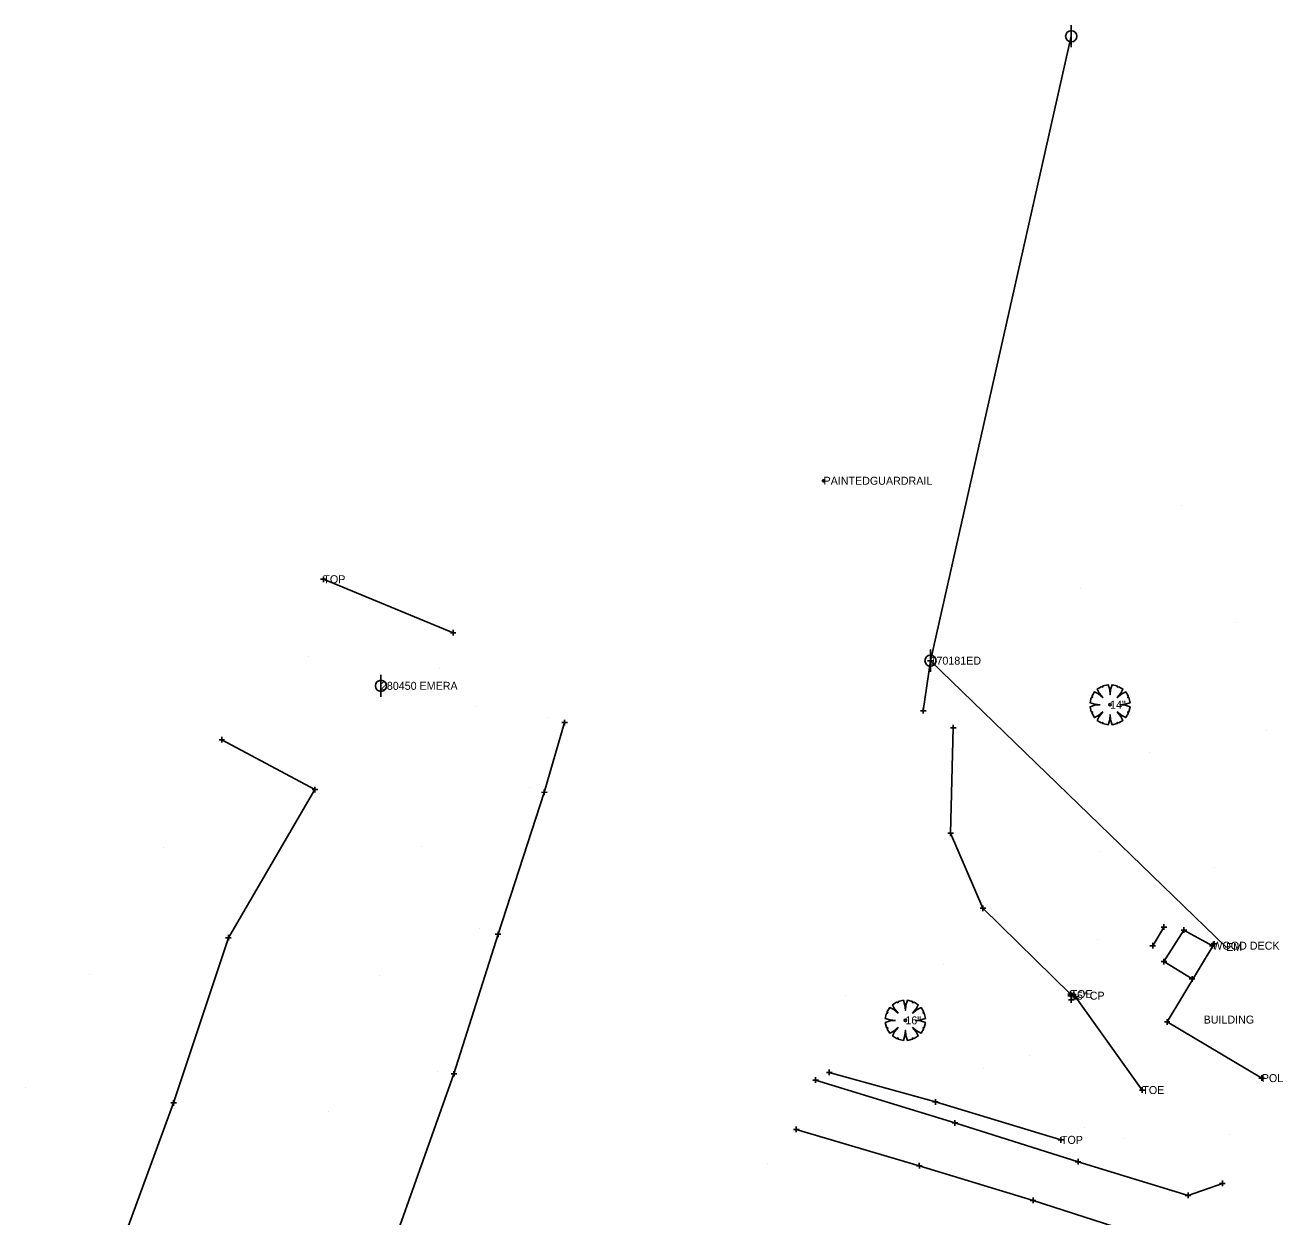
# Model space of a CAD drawing. Extents: x 1738496 to 1739092, y 463766 to 465141.
# Drawn here: x 1738806.9 to 1739089.9, y 464872.7 to 465140.8 of the extents above; entities that cross this region are included whole.
import ezdxf

# ---------------------------------------------------------------- set-up
doc = ezdxf.new("R2010")
doc.units = 0
for name, color, linetype in [('D_Terrain_Breaklines', 7, 'Continuous'), ('Default', 7, 'Continuous'), ('S_Survey_Shot', 7, 'Continuous'), ('S_Terrain_Boundary', 7, 'Continuous'), ('S_Terrain_High_Points', 7, 'Continuous'), ('S_Terrain_Imported_Contours', 7, 'Continuous'), ('S_Terrain_Islands', 7, 'Continuous'), ('S_Terrain_Low_Points', 7, 'Continuous'), ('S_Terrain_Major_Contours', 7, 'Continuous'), ('S_Terrain_Major_Contours_Label', 7, 'Continuous'), ('S_Terrain_Minor_Contours', 7, 'Continuous'), ('S_Terrain_Minor_Contours_Label', 7, 'Continuous'), ('S_Terrain_Triangles', 7, 'Continuous'), ('S_Terrain_Voids', 7, 'Continuous'), ('S_Terrain_XSC', 7, 'Continuous')]:
    doc.layers.add(name, color=color, linetype=linetype)

msp = doc.modelspace()

# ---------------------------------------------------------------- linework, layer by layer
at = {"layer": 'D_Terrain_Breaklines'}
for p, q in [((1738980.41, 464892.41), (1739008.09, 464884.24)), ((1739008.09, 464884.24), (1739033.68, 464876.41)), ((1739033.68, 464876.41), (1739056.49, 464869.05))]:
    msp.add_line(p, q, dxfattribs=at)
msp.add_lwpolyline([(1739076.28, 464880.26), (1739068.55, 464877.55), (1739043.79, 464885.13), (1739016.1, 464893.87), (1738984.76, 464903.48)], dxfattribs=at)
at = {"layer": 'Default'}
for p, q in [((1739042.26, 465138.34), (1739042.26, 465138.35)), ((1739042.26, 465138.34), (1739042.26, 465138.35)), ((1739042.26, 465138.34), (1739042.26, 465138.34)), ((1739010.6, 464997.86), (1739010.6, 464997.86)), ((1739010.6, 464997.86), (1739010.6, 464997.86)), ((1739010.6, 464997.86), (1739010.6, 464997.86)), ((1739010.6, 464997.86), (1739010.6, 464997.86)), ((1739010.6, 464997.86), (1739010.6, 464997.86)), ((1739010.6, 464997.86), (1739010.6, 464997.86)), ((1738886.97, 464992.2), (1738886.98, 464992.2)), ((1738886.98, 464992.2), (1738886.97, 464992.2)), ((1738886.97, 464992.2), (1738886.97, 464992.2)), ((1739077.07, 464933.44), (1739077.08, 464933.45)), ((1739077.08, 464933.44), (1739077.07, 464933.45)), ((1739077.08, 464933.44), (1739077.08, 464933.44)), ((1739042.22, 464922.49), (1739042.22, 464922.49))]:
    msp.add_line(p, q, dxfattribs=at)
for points in [[(1739042.26, 465138.34), (1739010.6, 464997.86)], [(1739077.08, 464933.44), (1739010.6, 464997.86)]]:
    msp.add_lwpolyline(points, dxfattribs=at)
for centre in [(1739042.26, 465138.34), (1739010.6, 464997.86), (1739010.6, 464997.86), (1738886.97, 464992.2), (1739077.08, 464933.44)]:
    msp.add_circle(centre, 0.00528, dxfattribs=at)
at = {"layer": 'S_Terrain_Boundary'}
msp.add_lwpolyline([(1739074.01, 464933.74), (1739067.6, 464937.25), (1739063.12, 464930.15), (1739069.47, 464926.26)], dxfattribs=at)
at = {"layer": 'S_Terrain_High_Points'}
msp.add_lwpolyline([(1739008.99, 464986.6), (1739010.6, 464997.86)], dxfattribs=at)
at = {"layer": 'S_Terrain_Imported_Contours'}
msp.add_lwpolyline([(1739063.13, 464937.93), (1739060.6, 464933.73)], dxfattribs=at)
at = {"layer": 'S_Terrain_Islands'}
msp.add_lwpolyline([(1739074.38, 464934.15), (1739063.84, 464916.59), (1739085.13, 464903.95)], dxfattribs=at)
at = {"layer": 'S_Terrain_Low_Points'}
for points in [[(1738874.03, 465016.18), (1738903.23, 465004.15)], [(1738869.35, 464800.24), (1738879.93, 464834.63), (1738890.41, 464868.41), (1738903.41, 464904.91), (1738913.32, 464936.3), (1738923.72, 464968.23), (1738928.3, 464983.93)], [(1739042.11, 464922.84), (1739022.39, 464942.17), (1739015.14, 464959.02), (1739015.74, 464982.78)], [(1738819.42, 464844.3), (1738827.65, 464863.8), (1738840.34, 464898.36), (1738852.67, 464935.54), (1738872.14, 464968.86), (1738851.19, 464980.06)], [(1739058.25, 464901.26), (1739043.21, 464922.24)], [(1739039.95, 464890.05), (1739011.71, 464898.59), (1738987.82, 464905.21)]]:
    msp.add_lwpolyline(points, dxfattribs=at)
at = {"layer": 'S_Terrain_Major_Contours'}
for p, q in [((1739041.47, 464922.49), (1739042.97, 464922.49)), ((1739042.22, 464923.24), (1739042.22, 464921.74))]:
    msp.add_line(p, q, dxfattribs=at)
at = {"layer": 'S_Terrain_Major_Contours_Label'}
for points in [[(1739048.74, 464987.95), (1739047.57, 464988.04), (1739046.49, 464988.4), (1739046.76, 464989.57), (1739047.03, 464989.57), (1739046.94, 464989.93), (1739047.48, 464990.83), (1739048.38, 464990.38), (1739049.37, 464989.57), (1739048.56, 464990.56), (1739048.11, 464991.46), (1739049.01, 464992.01), (1739049.37, 464991.91), (1739049.37, 464992.19), (1739050.55, 464992.46), (1739050.91, 464991.37), (1739051, 464990.2), (1739051.09, 464991.37), (1739051.45, 464992.46), (1739052.62, 464992.19), (1739052.62, 464991.91), (1739052.98, 464992.01), (1739053.88, 464991.46), (1739053.43, 464990.56), (1739052.62, 464989.57), (1739053.61, 464990.38), (1739054.52, 464990.83), (1739055.06, 464989.93), (1739054.97, 464989.57), (1739055.24, 464989.57), (1739055.51, 464988.4), (1739054.43, 464988.04), (1739053.25, 464987.95), (1739054.43, 464987.86), (1739055.51, 464987.49), (1739055.24, 464986.32), (1739054.97, 464986.32), (1739055.06, 464985.96), (1739054.52, 464985.06), (1739053.61, 464985.51), (1739052.62, 464986.32), (1739053.43, 464985.33), (1739053.88, 464984.43), (1739052.98, 464983.88), (1739052.62, 464983.98), (1739052.62, 464983.7), (1739051.45, 464983.43), (1739051.09, 464984.52), (1739051, 464985.69), (1739050.91, 464984.52), (1739050.55, 464983.43), (1739049.37, 464983.7), (1739049.37, 464983.98), (1739049.01, 464983.88), (1739048.11, 464984.43), (1739048.56, 464985.33), (1739049.37, 464986.32), (1739048.38, 464985.51), (1739047.48, 464985.06), (1739046.94, 464985.96), (1739047.03, 464986.32), (1739046.76, 464986.32), (1739046.49, 464987.49), (1739047.57, 464987.86), (1739048.74, 464987.95)], [(1739002.7, 464916.94), (1739001.52, 464917.03), (1739000.44, 464917.39), (1739000.71, 464918.56), (1739000.98, 464918.56), (1739000.89, 464918.93), (1739001.43, 464919.83), (1739002.34, 464919.38), (1739003.33, 464918.56), (1739002.52, 464919.56), (1739002.07, 464920.46), (1739002.97, 464921), (1739003.33, 464920.91), (1739003.33, 464921.18), (1739004.5, 464921.45), (1739004.86, 464920.37), (1739004.95, 464919.2), (1739005.04, 464920.37), (1739005.4, 464921.45), (1739006.58, 464921.18), (1739006.58, 464920.91), (1739006.94, 464921), (1739007.84, 464920.46), (1739007.39, 464919.56), (1739006.58, 464918.56), (1739007.57, 464919.38), (1739008.47, 464919.83), (1739009.01, 464918.93), (1739008.92, 464918.56), (1739009.19, 464918.56), (1739009.46, 464917.39), (1739008.38, 464917.03), (1739007.21, 464916.94), (1739008.38, 464916.85), (1739009.46, 464916.49), (1739009.19, 464915.32), (1739008.92, 464915.32), (1739009.01, 464914.96), (1739008.47, 464914.05), (1739007.57, 464914.5), (1739006.58, 464915.32), (1739007.39, 464914.32), (1739007.84, 464913.42), (1739006.94, 464912.88), (1739006.58, 464912.97), (1739006.58, 464912.7), (1739005.4, 464912.43), (1739005.04, 464913.51), (1739004.95, 464914.69), (1739004.86, 464913.51), (1739004.5, 464912.43), (1739003.33, 464912.7), (1739003.33, 464912.97), (1739002.97, 464912.88), (1739002.07, 464913.42), (1739002.52, 464914.32), (1739003.33, 464915.32), (1739002.34, 464914.5), (1739001.43, 464914.05), (1739000.89, 464914.96), (1739000.98, 464915.32), (1739000.71, 464915.32), (1739000.44, 464916.49), (1739001.52, 464916.85), (1739002.7, 464916.94)]]:
    msp.add_lwpolyline(points, dxfattribs=at)
for centre in [(1739051, 464987.95), (1739004.95, 464916.94)]:
    msp.add_circle(centre, 0.283, dxfattribs=at)
at = {"layer": 'S_Terrain_Minor_Contours'}
for p, q in [((1739042.26, 465140.84), (1739042.26, 465135.85)), ((1739010.6, 465000.36), (1739010.6, 464995.37)), ((1738886.97, 464994.69), (1738886.97, 464989.7))]:
    msp.add_line(p, q, dxfattribs=at)
for centre in [(1739042.26, 465138.34), (1739010.6, 464997.86), (1738886.97, 464992.2)]:
    msp.add_circle(centre, 1.25, dxfattribs=at)
at = {"layer": 'S_Terrain_Minor_Contours_Label'}
for p, q in [((1738986.94, 465038.34), (1738986.15, 465038.34)), ((1738986.81, 465038.08), (1738986.28, 465038.6)), ((1738986.81, 465038.6), (1738986.28, 465038.08)), ((1738986.54, 465038.73), (1738986.54, 465037.95))]:
    msp.add_line(p, q, dxfattribs=at)
at = {"layer": 'S_Terrain_Triangles'}
for p, q in [((1739067.15, 465032.82), (1739067.15, 465032.82)), ((1739044.39, 465014.12), (1739044.39, 465014.12)), ((1739079.23, 465006.55), (1739079.23, 465006.55)), ((1738870.6, 464998.78), (1738870.6, 464998.78)), ((1738900.22, 464996.07), (1738900.22, 464996.07)), ((1738908.56, 464987.54), (1738908.56, 464987.54)), ((1738924.45, 464985), (1738924.45, 464985)), ((1739086.11, 464982.21), (1739086.11, 464982.21)), ((1739059.88, 464977.11), (1739059.88, 464977.11)), ((1738920.41, 464969.34), (1738920.41, 464969.34)), ((1738837.99, 464955.81), (1738837.99, 464955.81)), ((1738896.21, 464956), (1738896.21, 464956)), ((1739048.53, 464954.9), (1739048.53, 464954.9)), ((1739074.58, 464951.31), (1739074.58, 464951.31)), ((1738909.16, 464937.5), (1738909.16, 464937.5)), ((1739048.13, 464935.24), (1739048.13, 464935.24)), ((1739013.45, 464929.43), (1739013.45, 464929.43)), ((1738821.49, 464927.35), (1738821.49, 464927.35)), ((1738886.64, 464927.13), (1738886.64, 464927.13)), ((1738991.39, 464922.63), (1738991.39, 464922.63)), ((1739032.84, 464909.05), (1739032.84, 464909.05)), ((1738899.6, 464905.5), (1738899.6, 464905.5)), ((1739022.63, 464906.13), (1739022.63, 464906.13)), ((1738806.94, 464901.74), (1738806.94, 464901.74)), ((1738875.13, 464896.53), (1738875.13, 464896.53)), ((1739045.35, 464892.84), (1739045.35, 464892.84)), ((1739077.88, 464891.18), (1739077.88, 464891.18)), ((1739054.32, 464890.26), (1739054.32, 464890.26)), ((1738973.94, 464884.68), (1738973.94, 464884.68))]:
    msp.add_line(p, q, dxfattribs=at)
at = {"layer": 'S_Terrain_Voids'}
msp.add_line((1739042.26, 464921.52), (1739042.26, 464921.52), dxfattribs=at)
at = {"layer": 'S_Terrain_XSC'}
for p, q in [((1738873.4, 465016.18), (1738874.67, 465016.18)), ((1738874.04, 465015.54), (1738874.03, 465016.82)), ((1738874.03, 465016.18), (1738874.03, 465016.18)), ((1738902.59, 465004.14), (1738903.86, 465004.15)), ((1738903.23, 465003.51), (1738903.23, 465004.78)), ((1738903.23, 465004.15), (1738903.23, 465004.15)), ((1739010.6, 464997.22), (1739010.6, 464998.5)), ((1739009.96, 464997.86), (1739011.24, 464997.86)), ((1739010.6, 464997.86), (1739010.6, 464997.86)), ((1739008.99, 464985.97), (1739008.99, 464987.24)), ((1738928.3, 464983.3), (1738928.29, 464984.57)), ((1739008.36, 464986.6), (1739009.63, 464986.6)), ((1739008.99, 464986.6), (1739008.99, 464986.6)), ((1738927.66, 464983.93), (1738928.93, 464983.93)), ((1738928.3, 464983.93), (1738928.3, 464983.93)), ((1739015.1, 464982.78), (1739016.37, 464982.78)), ((1739015.74, 464982.14), (1739015.74, 464983.42)), ((1739015.74, 464982.78), (1739015.74, 464982.78)), ((1738850.55, 464980.06), (1738851.82, 464980.06)), ((1738851.19, 464979.42), (1738851.19, 464980.7)), ((1738851.19, 464980.06), (1738851.19, 464980.06)), ((1738871.5, 464968.85), (1738872.78, 464968.86)), ((1738872.14, 464968.22), (1738872.14, 464969.49)), ((1738872.14, 464968.86), (1738872.14, 464968.86)), ((1738923.08, 464968.23), (1738924.36, 464968.24)), ((1738923.72, 464967.6), (1738923.72, 464968.87)), ((1738923.72, 464968.23), (1738923.72, 464968.23)), ((1739014.51, 464959.02), (1739015.78, 464959.02)), ((1739015.14, 464958.38), (1739015.14, 464959.65)), ((1739015.14, 464959.02), (1739015.14, 464959.02)), ((1739021.75, 464942.17), (1739023.03, 464942.17)), ((1739022.39, 464941.53), (1739022.39, 464942.81)), ((1739022.39, 464942.17), (1739022.39, 464942.17)), ((1738852.67, 464934.9), (1738852.67, 464936.17)), ((1738912.69, 464936.3), (1738913.96, 464936.3)), ((1738913.33, 464935.66), (1738913.32, 464936.93)), ((1738913.32, 464936.3), (1738913.32, 464936.3)), ((1739062.5, 464937.93), (1739063.77, 464937.93)), ((1739063.13, 464937.29), (1739063.13, 464938.56)), ((1739063.13, 464937.93), (1739063.13, 464937.93)), ((1739066.96, 464937.25), (1739068.24, 464937.25)), ((1739067.6, 464936.61), (1739067.6, 464937.88)), ((1739067.6, 464937.25), (1739067.6, 464937.25)), ((1738852.04, 464935.54), (1738853.31, 464935.54)), ((1738852.67, 464935.54), (1738852.67, 464935.54)), ((1739059.96, 464933.73), (1739061.23, 464933.73)), ((1739060.6, 464933.1), (1739060.6, 464934.37)), ((1739060.6, 464933.73), (1739060.6, 464933.73)), ((1739073.38, 464933.74), (1739074.65, 464933.74)), ((1739073.74, 464934.15), (1739075.01, 464934.15)), ((1739074.01, 464933.11), (1739074.01, 464934.38)), ((1739074.01, 464933.74), (1739074.01, 464933.74)), ((1739074.38, 464933.52), (1739074.38, 464934.79)), ((1739074.38, 464934.15), (1739074.38, 464934.15)), ((1739063.12, 464929.52), (1739063.12, 464930.79)), ((1739062.49, 464930.15), (1739063.76, 464930.15)), ((1739063.12, 464930.15), (1739063.12, 464930.15)), ((1739068.83, 464926.26), (1739070.1, 464926.26)), ((1739069.47, 464925.62), (1739069.47, 464926.9)), ((1739069.47, 464926.26), (1739069.47, 464926.26)), ((1739041.48, 464922.84), (1739042.75, 464922.84)), ((1739042.11, 464922.2), (1739042.11, 464923.47)), ((1739042.11, 464922.84), (1739042.11, 464922.84)), ((1739042.26, 464920.88), (1739042.26, 464922.16)), ((1739042.57, 464922.24), (1739043.84, 464922.24)), ((1739043.21, 464921.6), (1739043.21, 464922.88)), ((1739043.21, 464922.24), (1739043.21, 464922.24)), ((1739041.62, 464921.52), (1739042.89, 464921.52)), ((1739042.26, 464921.52), (1739042.26, 464921.52)), ((1739063.21, 464916.59), (1739064.48, 464916.59)), ((1739063.84, 464915.95), (1739063.84, 464917.22)), ((1739063.84, 464916.59), (1739063.84, 464916.59)), ((1738902.78, 464904.91), (1738904.05, 464904.91)), ((1738903.42, 464904.27), (1738903.41, 464905.54)), ((1738903.41, 464904.91), (1738903.41, 464904.91)), ((1738987.19, 464905.21), (1738988.46, 464905.21)), ((1738987.83, 464904.58), (1738987.82, 464905.85)), ((1738987.82, 464905.21), (1738987.82, 464905.21)), ((1738984.12, 464903.48), (1738985.4, 464903.49)), ((1738984.76, 464902.85), (1738984.76, 464904.12)), ((1738984.76, 464903.48), (1738984.76, 464903.48)), ((1739084.49, 464903.95), (1739085.77, 464903.95)), ((1739085.13, 464903.32), (1739085.13, 464904.59)), ((1739085.13, 464903.95), (1739085.13, 464903.95)), ((1739011.71, 464897.96), (1739011.71, 464899.23)), ((1739057.61, 464901.26), (1739058.89, 464901.26)), ((1739058.25, 464900.63), (1739058.25, 464901.9)), ((1739058.25, 464901.26), (1739058.25, 464901.26)), ((1738839.7, 464898.35), (1738840.97, 464898.36)), ((1738840.34, 464897.72), (1738840.34, 464898.99)), ((1738840.34, 464898.36), (1738840.34, 464898.36)), ((1739011.07, 464898.59), (1739012.34, 464898.59)), ((1739011.71, 464898.59), (1739011.71, 464898.59)), ((1739015.46, 464893.87), (1739016.74, 464893.87)), ((1739016.1, 464893.23), (1739016.1, 464894.51)), ((1739016.1, 464893.87), (1739016.1, 464893.87)), ((1738979.78, 464892.41), (1738981.05, 464892.41)), ((1738980.42, 464891.77), (1738980.41, 464893.04)), ((1738980.41, 464892.41), (1738980.41, 464892.41)), ((1739039.95, 464889.41), (1739039.95, 464890.68)), ((1739039.31, 464890.04), (1739040.58, 464890.05)), ((1739039.95, 464890.05), (1739039.95, 464890.05)), ((1739043.16, 464885.13), (1739044.43, 464885.14)), ((1739043.79, 464884.5), (1739043.79, 464885.77)), ((1739043.79, 464885.13), (1739043.79, 464885.13)), ((1739007.46, 464884.24), (1739008.73, 464884.24)), ((1739008.1, 464883.6), (1739008.09, 464884.88)), ((1739008.09, 464884.24), (1739008.09, 464884.24)), ((1739075.65, 464880.26), (1739076.92, 464880.26)), ((1739076.28, 464879.63), (1739076.28, 464880.9)), ((1739076.28, 464880.26), (1739076.28, 464880.26)), ((1739033.68, 464875.78), (1739033.67, 464877.05)), ((1739067.92, 464877.55), (1739069.19, 464877.56)), ((1739068.55, 464876.92), (1739068.55, 464878.19)), ((1739068.55, 464877.55), (1739068.55, 464877.55)), ((1739033.04, 464876.41), (1739034.31, 464876.42)), ((1739033.68, 464876.41), (1739033.68, 464876.41))]:
    msp.add_line(p, q, dxfattribs=at)

# ---------------------------------------------------------------- texts
at = {"layer": 'S_Survey_Shot'}
for s, p in [('PAINTEDGUARDRAIL', (1738986.54, 465037.44)), ('TOP', (1738874.03, 465015.28)), ('170181ED', (1739010.6, 464996.96)), ('170181ED', (1739010.6, 464996.96)), ('170181ED', (1739010.6, 464996.96)), ('170181ED', (1739010.6, 464996.96)), ('280450 EMERA', (1738886.97, 464991.3)), ('280450 EMERA', (1738886.97, 464991.3)), ('14"', (1739051, 464987.05)), ('WOOD DECK', (1739074.01, 464932.84)), ('EM', (1739077.08, 464932.54)), ('TOE', (1739042.11, 464921.94)), ('15" CP', (1739042.22, 464921.59)), ('16"', (1739004.95, 464916.04)), ('BUILDING', (1739072.05, 464916.21)), ('POL', (1739085.13, 464903.05)), ('TOE', (1739058.25, 464900.36)), ('TOP', (1739039.95, 464889.15))]:
    msp.add_text(s, height=1.8, dxfattribs=at).set_placement(p)

doc.saveas('drawing.dxf')
